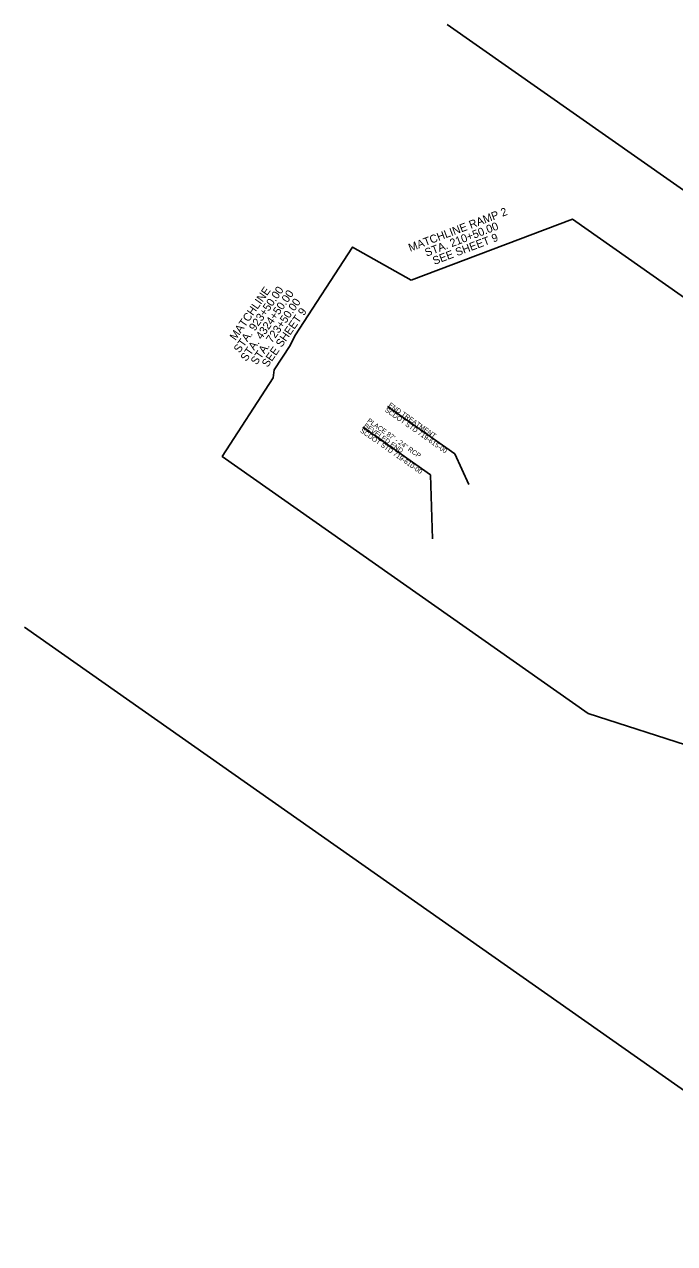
# Model space of a CAD drawing. Extents: x 2221439 to 2223471, y 467578 to 469482.
# Drawn here: x 2221439 to 2222455, y 467578 to 469482 of the extents above; entities that cross this region are included whole.
import ezdxf

# ---------------------------------------------------------------- set-up
doc = ezdxf.new("R2010")
doc.units = 0
for name, color, linetype in [('RD_HY_Misc', 7, 'Continuous'), ('RD_SHT_MatchLine', 7, 'Continuous'), ('RD_SHT_ShtClip', 7, 'Continuous'), ('RD_SHT_TX', 7, 'Continuous')]:
    doc.layers.add(name, color=color, linetype=linetype)

msp = doc.modelspace()

# ---------------------------------------------------------------- linework, layer by layer
at = {"layer": 'RD_HY_Misc'}
for p, q in [((2222111.7, 468811.4), (2222006.6, 468885.2)), ((2222073.6, 468778.7), (2221968, 468852.9))]:
    msp.add_line(p, q, dxfattribs=at)
for points in [[(2222111.7, 468811.4), (2222133.6, 468763.3)], [(2222073.6, 468778.7), (2222076.6, 468678.8)]]:
    msp.add_lwpolyline(points, dxfattribs=at)
at = {"layer": 'RD_SHT_MatchLine'}
msp.add_line((2222043.7, 469082.4), (2222295.6, 469177.9), dxfattribs=at)
msp.add_lwpolyline([(2221952, 469134.1), (2221862, 468995.5), (2221854.3, 468980.4), (2221829.7, 468942.5), (2221827.8, 468929.8), (2221748.3, 468807.4)], dxfattribs=at)
at = {"layer": 'RD_SHT_ShtClip'}
msp.add_lwpolyline([(2222043.7, 469082.4), (2222295.6, 469177.9), (2223317.8, 468460.2), (2223094.6, 468142.3), (2223088.2, 468126.5), (2223070, 468100.4), (2223066.6, 468082.9), (2222999.3, 467986.9), (2222931.9, 467891), (2222600.7, 468123.6), (2222656.6, 468297.6), (2222320.1, 468406), (2221748.3, 468807.4), (2221827.8, 468929.8), (2221829.7, 468942.5), (2221854.3, 468980.4), (2221862, 468995.5), (2221952, 469134.1)], close=True, dxfattribs=at)
at = {"layer": 'RD_SHT_TX'}
for p, q in [((2223470.9, 468519.5), (2222100, 469481.9)), ((2221439.3, 468540.7), (2222810.1, 467578.3))]:
    msp.add_line(p, q, dxfattribs=at)

# ---------------------------------------------------------------- texts
at = {"layer": 'RD_HY_Misc'}
for s, p in [('END TREATMENT', (2222007.1, 468886)), ('SCDOT STD 719-615-00', (2222001.7, 468878.2)), ('SCDOT STD 719-610-00', (2221963.1, 468845.9)), ('BEVELED END', (2221968.6, 468853.7)), ('PLACE 87\' - 24" RCP', (2221974, 468861.5))]:
    msp.add_text(s, height=7.5, rotation=324.929, dxfattribs=at).set_placement(p)
at = {"layer": 'RD_SHT_MatchLine'}
for s, rotation, p in [('MATCHLINE RAMP 2', 20.7664, (2222042, 469126.8)), ('STA. 210+50.00', 20.7664, (2222067.6, 469119.1)), ('SEE SHEET 9', 20.7664, (2222079.8, 469106.3)), ('MATCHLINE', 54.929, (2221769.1, 468987.5)), ('STA. 923+50.00', 54.929, (2221775.3, 468968)), ('STA. 4324+50.00', 54.929, (2221785.9, 468954.8)), ('STA. 723+50.00', 54.929, (2221801.9, 468949.3)), ('SEE SHEET 9', 54.929, (2221819.2, 468945.6))]:
    msp.add_text(s, height=12.5, rotation=rotation, dxfattribs=at).set_placement(p)

doc.saveas('drawing.dxf')
